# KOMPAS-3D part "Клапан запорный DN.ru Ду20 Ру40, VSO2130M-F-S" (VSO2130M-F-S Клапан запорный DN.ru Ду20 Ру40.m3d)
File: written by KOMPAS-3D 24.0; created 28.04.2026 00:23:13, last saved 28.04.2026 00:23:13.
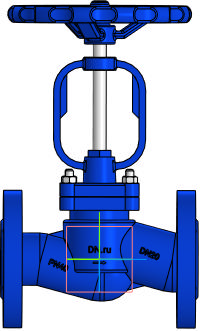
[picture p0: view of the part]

Document properties: Автор: DN.ru; Полное имя файла: C:\Работа\ГОТОВЫЕ ИСХОДНИКИ\VSO2130M-F-S Клапан запорный сальниковый DN.ru Ду15-100 Ру40\DN20\VSO2130M-F-S Клапан запорный DN.ru Ду20 Ру40.m3d

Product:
- Part/product: Клапан запорный DN.ru Ду20 Ру40  | designation VSO2130M-F-S
    Масса: 4.5
    Раздел спецификации: Прочие изделия
    Примечание: D090-01980

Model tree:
1. Операция без истории:1

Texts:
  VSO2130M-F-S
